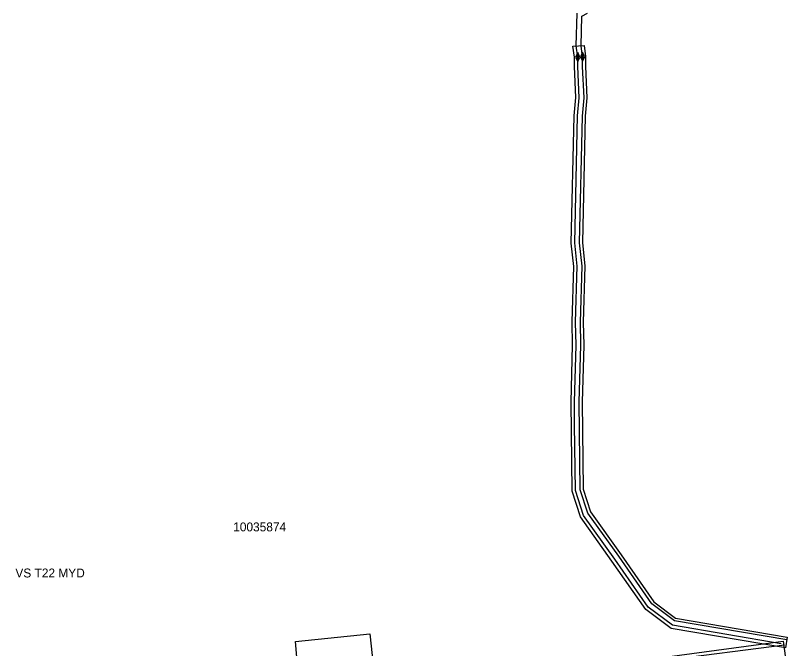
# Model space of a CAD drawing. Extents: x -763120 to -760227, y -1155882 to -1151394.
# Drawn here: x -762626 to -762539.2, y -1152714.2 to -1152643 of the extents above; entities that cross this region are included whole.
import ezdxf

# ---------------------------------------------------------------- set-up
doc = ezdxf.new("R2010")
doc.units = 0
for name, color, linetype in [('Vrstva 19', 7, 'Continuous'), ('Vrstva 20', 7, 'Continuous'), ('Vrstva 26', 7, 'Continuous'), ('Vrstva 27', 7, 'Continuous'), ('Vrstva 35', 7, 'Continuous'), ('Vrstva 4', 7, 'Continuous'), ('Vrstva 5', 7, 'Continuous')]:
    doc.layers.add(name, color=color, linetype=linetype)

# ---------------------------------------------------------------- blocks, each defined once
blk = doc.blocks.new('VN870')
at = {"layer": 'Vrstva 4'}
for points in [[(0, -0.25), (0.5, 0.002), (0, 0.25), (-0.5, 0.002), (0, -0.25)], [(0.37, -0.002), (0, 0.187), (-0.362, 0.002), (0, -0.187), (0.37, -0.002)], [(0.244, -0.002), (0, 0.124), (-0.252, -0.002), (0, -0.124), (0.244, -0.002)], [(0.122, -0.002), (0, 0.061), (-0.13, -0.002), (0, -0.061), (0.122, -0.002)]]:
    blk.add_lwpolyline(points, dxfattribs=at)

msp = doc.modelspace()

# ---------------------------------------------------------------- linework, layer by layer
at = {"layer": 'Vrstva 20'}
for points in [[(-762562.084, -1152646.417), (-762561.925, -1152647.655), (-762561.925, -1152648.76), (-762561.764, -1152652.296), (-762561.936, -1152654.366), (-762562.264, -1152668.564), (-762561.984, -1152671.196), (-762562.165, -1152677.494), (-762562.115, -1152680.094), (-762562.295, -1152686.499), (-762562.187, -1152696.289), (-762561.368, -1152698.826), (-762557.923, -1152703.641), (-762554.241, -1152708.93), (-762551.78, -1152710.762), (-762539.225, -1152712.897), (-762539.434, -1152714.125), (-762552.284, -1152711.94), (-762555.147, -1152709.808), (-762558.941, -1152704.359), (-762562.494, -1152699.393), (-762563.43, -1152696.492), (-762563.541, -1152686.486), (-762563.361, -1152680.088), (-762563.411, -1152677.488), (-762563.231, -1152671.245), (-762563.511, -1152668.616), (-762563.18, -1152654.3), (-762563.011, -1152652.273), (-762563.171, -1152648.789), (-762563.171, -1152647.734), (-762563.331, -1152646.479)], [(-762552.749, -1152715.142), (-762539.689, -1152713.352), (-762539.199, -1152716.926), (-762552.259, -1152718.716)]]:
    msp.add_lwpolyline(points, close=True, dxfattribs=at)
at = {"layer": 'Vrstva 35'}
msp.add_lwpolyline([(-762585.648, -1152717.41), (-762584.54, -1152728.61), (-762584.094, -1152734.266), (-762592.523, -1152735.497), (-762593.007, -1152729.361), (-762594.107, -1152718.247), (-762594.53, -1152713.407), (-762586.171, -1152712.547)], close=True, dxfattribs=at)
at = {"layer": 'Vrstva 5'}
for points in [[(-762539.924, -1152713.653), (-762552.13, -1152711.58), (-762554.87, -1152709.54), (-762558.63, -1152704.14), (-762562.15, -1152699.22), (-762563.05, -1152696.43), (-762563.14, -1152689.03), (-762563.16, -1152686.49), (-762562.98, -1152680.09), (-762563.03, -1152677.49), (-762562.85, -1152671.23), (-762563.13, -1152668.6), (-762562.8, -1152654.32), (-762562.63, -1152652.28), (-762562.79, -1152648.78), (-762562.79, -1152647.71), (-762562.95, -1152646.46), (-762562.85, -1152642.78)], [(-762539.278, -1152713.21), (-762551.908, -1152711.062), (-762554.472, -1152709.154), (-762558.183, -1152703.824), (-762561.655, -1152698.971), (-762562.503, -1152696.341), (-762562.612, -1152686.496), (-762562.432, -1152680.092), (-762562.482, -1152677.493), (-762562.302, -1152671.209), (-762562.582, -1152668.577), (-762562.253, -1152654.349), (-762562.081, -1152652.29), (-762562.242, -1152648.767), (-762562.242, -1152647.675), (-762562.401, -1152646.433), (-762562.311, -1152643.109), (-762561.709, -1152642.777)], [(-762539.553, -1152713.809), (-762553.008, -1152715.532), (-762555.722, -1152716.587), (-762563.244, -1152717.709), (-762572.873, -1152718.754), (-762577.842, -1152718.513), (-762579.941, -1152719.444), (-762581.765, -1152722.888), (-762584.877, -1152732.608), (-762587.96, -1152741.27), (-762591.207, -1152749.42), (-762592.031, -1152750.283), (-762598.622, -1152752.984), (-762600.145, -1152753.917), (-762601.457, -1152754.386), (-762604.152, -1152755.579), (-762605.05, -1152755.313), (-762607.679, -1152755.615), (-762610.32, -1152752.03), (-762610.935, -1152752.831)]]:
    msp.add_lwpolyline(points, dxfattribs=at)

# ---------------------------------------------------------------- block references
at = {"layer": 'Vrstva 19', "rotation": 90}
for p in [(-762562.79, -1152647.71), (-762562.242, -1152647.675)]:
    msp.add_blockref('VN870', p, dxfattribs=at)

# ---------------------------------------------------------------- texts
at = {"layer": 'Vrstva 26'}
msp.add_text('10035874', height=1, dxfattribs=at).set_placement((-762601.525, -1152701.023))
at = {"layer": 'Vrstva 27'}
msp.add_text('VS T22 MYD', height=1, dxfattribs=at).set_placement((-762626.016, -1152706.202))

doc.saveas('drawing.dxf')
